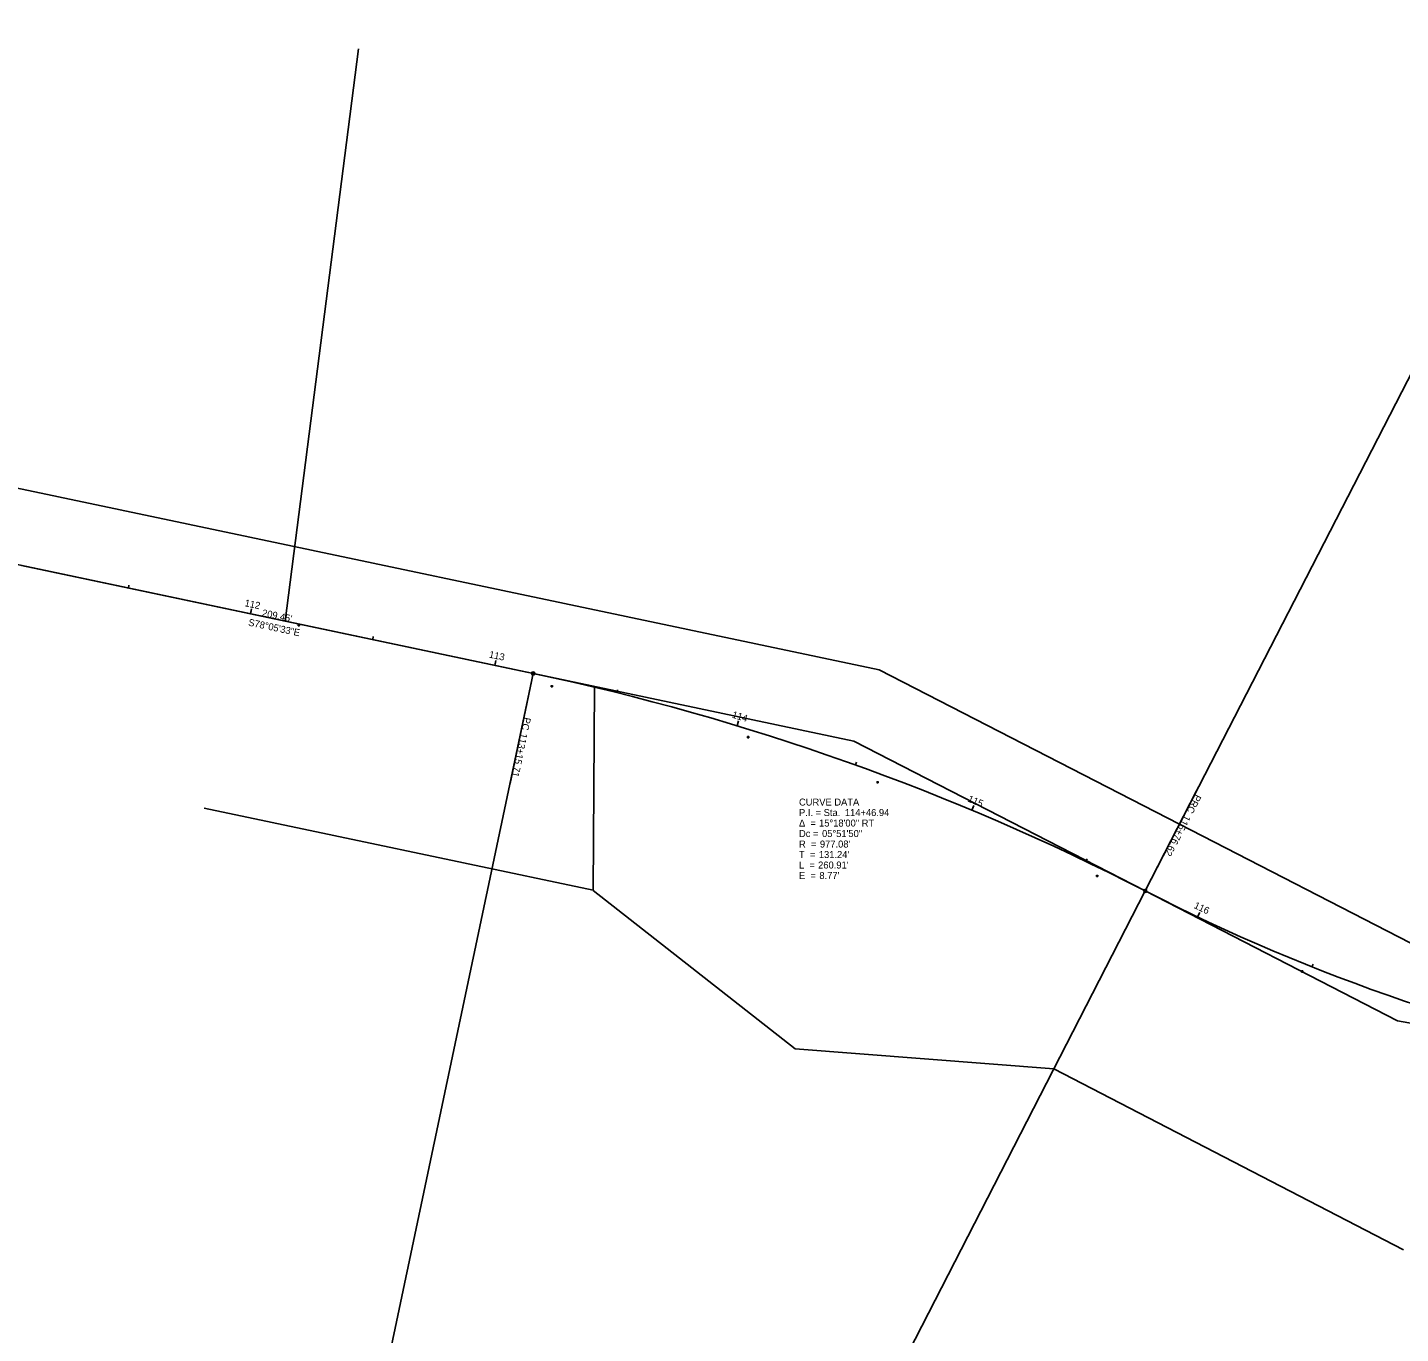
# Model space of a CAD drawing. Extents: x 2003596 to 2006888, y 571866 to 574416.
# Drawn here: x 2003884 to 2004434, y 572620 to 573143 of the extents above; entities that cross this region are included whole.
import ezdxf

# ---------------------------------------------------------------- set-up
doc = ezdxf.new("R2010")
doc.units = 0
for name, color, linetype in [('DV_X_Lot_Line', 7, 'Continuous'), ('GE_X_Alignment', 7, 'Continuous'), ('GE_X_Alignment_1000_Bearings', 7, 'Continuous'), ('GE_X_Alignment_1000_Cardinal_Points', 7, 'Continuous'), ('GE_X_Alignment_1000_Curve_Data', 7, 'Continuous'), ('GE_X_Alignment_1000_Distances', 7, 'Continuous'), ('GE_X_Alignment_1000_Stations', 7, 'Continuous'), ('GE_X_Alignment_100_Bearings', 7, 'Continuous'), ('GE_X_Alignment_100_Cardinal_Points', 7, 'Continuous'), ('GE_X_Alignment_100_Curve_Data', 7, 'Continuous'), ('GE_X_Alignment_100_Distances', 7, 'Continuous'), ('GE_X_Alignment_100_Stations', 7, 'Continuous'), ('GE_X_Alignment_500_Bearings', 7, 'Continuous'), ('GE_X_Alignment_500_Cardinal_Points', 7, 'Continuous'), ('GE_X_Alignment_500_Curve_Data', 7, 'Continuous'), ('GE_X_Alignment_500_Distances', 7, 'Continuous'), ('GE_X_Alignment_500_Stations', 7, 'Continuous'), ('RW_X_Esmt_SH', 7, 'Continuous'), ('SC_Scratch1', 7, 'Continuous'), ('SV_X_Random_Point', 7, 'Continuous'), ('SV_X_Shot_Marker', 7, 'Continuous')]:
    doc.layers.add(name, color=color, linetype=linetype)

msp = doc.modelspace()

# ---------------------------------------------------------------- linework, layer by layer
at = {"layer": 'DV_X_Lot_Line'}
msp.add_line((2004110.99, 572797.19), (2004111.48, 572878.85), dxfattribs=at)
at = {"layer": 'GE_X_Alignment'}
msp.add_line((2003882.01, 572927.27), (2004086.95, 572884.06), dxfattribs=at)
for centre, radius, start, end in [((2003885.35, 571928), 977.08, 62.79264, 78.09264), ((2004683.7, 573480.96), 769.07, 242.79359, 259.61026)]:
    msp.add_arc(centre, radius, start, end, dxfattribs=at)
at = {"layer": 'GE_X_Alignment_1000_Cardinal_Points'}
for p, q in [((2004086.95, 572884.06), (2004077.67, 572840.02)), ((2004332.08, 572796.97), (2004352.66, 572837))]:
    msp.add_line(p, q, dxfattribs=at)
for centre in [(2004086.95, 572884.06), (2004332.08, 572796.97)]:
    msp.add_circle(centre, 0.6, dxfattribs=at)
at = {"layer": 'GE_X_Alignment_1000_Stations'}
msp.add_line((2004262.64, 572829.3), (2004263.1, 572830.41), dxfattribs=at)
at = {"layer": 'GE_X_Alignment_100_Cardinal_Points'}
for p, q in [((2004086.95, 572884.06), (2004077.67, 572840.02)), ((2004332.08, 572796.97), (2004352.66, 572837))]:
    msp.add_line(p, q, dxfattribs=at)
for centre in [(2004086.95, 572884.06), (2004332.08, 572796.97)]:
    msp.add_circle(centre, 0.6, dxfattribs=at)
at = {"layer": 'GE_X_Alignment_100_Stations'}
for p, q in [((2003924.81, 572918.25), (2003925.06, 572919.42)), ((2003973.74, 572907.93), (2003974.15, 572909.89)), ((2004022.66, 572897.61), (2004022.91, 572898.79)), ((2004071.58, 572887.3), (2004072, 572889.25)), ((2004120.38, 572876.39), (2004120.67, 572877.56)), ((2004168.58, 572863.13), (2004169.16, 572865.04)), ((2004216.04, 572847.42), (2004216.45, 572848.55)), ((2004262.64, 572829.3), (2004263.41, 572831.14)), ((2004308.25, 572808.82), (2004308.77, 572809.9)), ((2004353.04, 572786.6), (2004353.9, 572788.41)), ((2004398.85, 572766.59), (2004399.29, 572767.7))]:
    msp.add_line(p, q, dxfattribs=at)
at = {"layer": 'GE_X_Alignment_500_Cardinal_Points'}
for p, q in [((2004086.95, 572884.06), (2004077.67, 572840.02)), ((2004332.08, 572796.97), (2004352.66, 572837))]:
    msp.add_line(p, q, dxfattribs=at)
for centre in [(2004086.95, 572884.06), (2004332.08, 572796.97)]:
    msp.add_circle(centre, 0.6, dxfattribs=at)
at = {"layer": 'GE_X_Alignment_500_Stations'}
for p, q in [((2003973.74, 572907.93), (2003973.98, 572909.1)), ((2004071.58, 572887.3), (2004071.83, 572888.47)), ((2004168.58, 572863.13), (2004168.93, 572864.28)), ((2004262.64, 572829.3), (2004263.41, 572831.14)), ((2004353.04, 572786.6), (2004353.55, 572787.69))]:
    msp.add_line(p, q, dxfattribs=at)
at = {"layer": 'RW_X_Esmt_SH'}
for p, q in [((2003800.73, 572975.07), (2004225.49, 572885.5)), ((2004225.49, 572885.5), (2004345.8, 572823.66)), ((2003955.16, 572830.09), (2004110.99, 572797.23)), ((2004345.8, 572823.66), (2004442.88, 572773.75)), ((2004191.8, 572733.76), (2004110.99, 572797.19)), ((2004295.51, 572725.82), (2004191.8, 572733.76)), ((2004435.53, 572653.29), (2004295.51, 572725.82))]:
    msp.add_line(p, q, dxfattribs=at)
at = {"layer": 'SC_Scratch1'}
for p, q in [((2004683.7, 573480.96), (2004332.08, 572796.97)), ((2003987.65, 572905), (2004016.96, 573134.06)), ((2003794.54, 572945.72), (2004215.36, 572856.98)), ((2003885.35, 571928), (2004086.95, 572884.06)), ((2004215.36, 572856.98), (2004332.08, 572796.97)), ((2003885.35, 571928), (2004332.08, 572796.97)), ((2004332.08, 572796.97), (2004433.11, 572745.04)), ((2004433.11, 572745.04), (2005031.48, 572635.32))]:
    msp.add_line(p, q, dxfattribs=at)
at = {"layer": 'SV_X_Random_Point'}
for p, q in [((2004086.29, 572883.39), (2004087.62, 572884.72)), ((2004086.29, 572884.72), (2004087.62, 572883.39)), ((2004331.42, 572796.31), (2004332.75, 572797.64)), ((2004331.42, 572797.64), (2004332.75, 572796.31))]:
    msp.add_line(p, q, dxfattribs=at)
at = {"layer": 'SV_X_Shot_Marker'}
for p, q in [((2003992.57, 572903.41), (2003993.57, 572903.41)), ((2003993.07, 572903.91), (2003993.07, 572902.91)), ((2003993.07, 572903.41), (2003993.07, 572903.41)), ((2004093.93, 572878.92), (2004094.93, 572878.92)), ((2004094.43, 572879.42), (2004094.43, 572878.42)), ((2004094.43, 572878.92), (2004094.43, 572878.92)), ((2004172.52, 572858.53), (2004173.52, 572858.53)), ((2004173.02, 572859.03), (2004173.02, 572858.03)), ((2004173.02, 572858.53), (2004173.02, 572858.53)), ((2004224.38, 572840.48), (2004225.38, 572840.48)), ((2004224.88, 572840.98), (2004224.88, 572839.98)), ((2004224.88, 572840.48), (2004224.88, 572840.48)), ((2004312.33, 572802.99), (2004313.33, 572802.99)), ((2004312.83, 572803.49), (2004312.83, 572802.49)), ((2004312.83, 572802.99), (2004312.83, 572802.99)), ((2004394.44, 572764.71), (2004395.44, 572764.71)), ((2004394.94, 572765.21), (2004394.94, 572764.21)), ((2004394.94, 572764.71), (2004394.94, 572764.71))]:
    msp.add_line(p, q, dxfattribs=at)

# ---------------------------------------------------------------- texts
at = {"layer": 'GE_X_Alignment_1000_Bearings'}
msp.add_text('S78°05\'33"E', height=2.8, rotation=348.0925, dxfattribs=at).set_placement((2003972.65, 572903.25))
at = {"layer": 'GE_X_Alignment_1000_Cardinal_Points'}
for s, rotation, p in [('PC', 258.0926, (2004083.34, 572866.69)), ('113+15.71', 258.0926, (2004081.99, 572860.31)), ('PRC', 242.7936, (2004352.17, 572835.94)), ('115+76.62', 242.7936, (2004347.89, 572827.63))]:
    msp.add_text(s, height=2.8, rotation=rotation, dxfattribs=at).set_placement(p)
at = {"layer": 'GE_X_Alignment_1000_Curve_Data'}
for s, p in [('CURVE DATA', (2004193.4, 572831.16)), ('Δ  = ', (2004193.4, 572822.76)), ('P.I. = Sta. ', (2004193.4, 572826.96)), ('15°18\'00" RT', (2004201.43, 572822.76)), ('114+46.94', (2004211.77, 572826.96)), ('Dc = ', (2004193.4, 572818.56)), ('05°51\'50"', (2004202.64, 572818.56)), ('R  = ', (2004193.4, 572814.36)), ("977.08'", (2004201.77, 572814.36)), ('T  = ', (2004193.4, 572810.16)), ('L  = ', (2004193.4, 572805.96)), ("260.91'", (2004201.05, 572805.96)), ("131.24'", (2004201.34, 572810.16)), ('E  = ', (2004193.4, 572801.76)), ("8.77'", (2004201.56, 572801.76))]:
    msp.add_text(s, height=2.8, dxfattribs=at).set_placement(p)
at = {"layer": 'GE_X_Alignment_1000_Distances'}
msp.add_text("209.45'", height=2.8, rotation=348.0925, dxfattribs=at).set_placement((2003978.14, 572907.05))
at = {"layer": 'GE_X_Alignment_100_Bearings'}
msp.add_text('S78°05\'33"E', height=2.8, rotation=348.0925, dxfattribs=at).set_placement((2003972.65, 572903.25))
at = {"layer": 'GE_X_Alignment_100_Cardinal_Points'}
for s, rotation, p in [('PC', 258.0926, (2004083.34, 572866.69)), ('113+15.71', 258.0926, (2004081.99, 572860.31)), ('PRC', 242.7936, (2004352.17, 572835.94)), ('115+76.62', 242.7936, (2004347.89, 572827.63))]:
    msp.add_text(s, height=2.8, rotation=rotation, dxfattribs=at).set_placement(p)
at = {"layer": 'GE_X_Alignment_100_Curve_Data'}
for s, p in [('CURVE DATA', (2004193.4, 572831.16)), ('Δ  = ', (2004193.4, 572822.76)), ('P.I. = Sta. ', (2004193.4, 572826.96)), ('15°18\'00" RT', (2004201.43, 572822.76)), ('114+46.94', (2004211.77, 572826.96)), ('Dc = ', (2004193.4, 572818.56)), ('05°51\'50"', (2004202.64, 572818.56)), ('R  = ', (2004193.4, 572814.36)), ("977.08'", (2004201.77, 572814.36)), ('T  = ', (2004193.4, 572810.16)), ('L  = ', (2004193.4, 572805.96)), ("260.91'", (2004201.05, 572805.96)), ("131.24'", (2004201.34, 572810.16)), ('E  = ', (2004193.4, 572801.76)), ("8.77'", (2004201.56, 572801.76))]:
    msp.add_text(s, height=2.8, dxfattribs=at).set_placement(p)
at = {"layer": 'GE_X_Alignment_100_Distances'}
msp.add_text("209.45'", height=2.8, rotation=348.0925, dxfattribs=at).set_placement((2003978.14, 572907.05))
at = {"layer": 'GE_X_Alignment_100_Stations'}
for s, rotation, p in [('112', 348.0925, (2003971.19, 572911.02)), ('113', 348.0925, (2004069.06, 572890.43)), ('114', 343.1496, (2004166.34, 572866.42)), ('115', 337.2856, (2004260.72, 572832.86)), ('116', 334.5354, (2004351.3, 572790.25))]:
    msp.add_text(s, height=2.8, rotation=rotation, dxfattribs=at).set_placement(p)
at = {"layer": 'GE_X_Alignment_500_Bearings'}
msp.add_text('S78°05\'33"E', height=2.8, rotation=348.0925, dxfattribs=at).set_placement((2003972.65, 572903.25))
at = {"layer": 'GE_X_Alignment_500_Cardinal_Points'}
for s, rotation, p in [('PC', 258.0926, (2004083.34, 572866.69)), ('113+15.71', 258.0926, (2004081.99, 572860.31)), ('PRC', 242.7936, (2004352.17, 572835.94)), ('115+76.62', 242.7936, (2004347.89, 572827.63))]:
    msp.add_text(s, height=2.8, rotation=rotation, dxfattribs=at).set_placement(p)
at = {"layer": 'GE_X_Alignment_500_Curve_Data'}
for s, p in [('CURVE DATA', (2004193.4, 572831.16)), ('Δ  = ', (2004193.4, 572822.76)), ('P.I. = Sta. ', (2004193.4, 572826.96)), ('15°18\'00" RT', (2004201.43, 572822.76)), ('114+46.94', (2004211.77, 572826.96)), ('Dc = ', (2004193.4, 572818.56)), ('05°51\'50"', (2004202.64, 572818.56)), ('R  = ', (2004193.4, 572814.36)), ("977.08'", (2004201.77, 572814.36)), ('T  = ', (2004193.4, 572810.16)), ('L  = ', (2004193.4, 572805.96)), ("260.91'", (2004201.05, 572805.96)), ("131.24'", (2004201.34, 572810.16)), ('E  = ', (2004193.4, 572801.76)), ("8.77'", (2004201.56, 572801.76))]:
    msp.add_text(s, height=2.8, dxfattribs=at).set_placement(p)
at = {"layer": 'GE_X_Alignment_500_Distances'}
msp.add_text("209.45'", height=2.8, rotation=348.0925, dxfattribs=at).set_placement((2003978.14, 572907.05))
at = {"layer": 'GE_X_Alignment_500_Stations'}
msp.add_text('115', height=2.8, rotation=337.2856, dxfattribs=at).set_placement((2004260.72, 572832.86))

doc.saveas('drawing.dxf')
